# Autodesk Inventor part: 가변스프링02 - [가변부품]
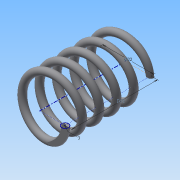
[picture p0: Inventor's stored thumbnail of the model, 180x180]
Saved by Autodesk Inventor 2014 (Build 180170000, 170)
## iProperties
Created: 2015-09
Part Number: 가변스프링02 - [가변부품]
Material: 강철, 탄소
Document SubType Name: Modeling
Designer: study
Density: 7.87 g/cm^3
Appearance: 반연마
Mass: 18.8856 g
Surface Area: 32.5491 cm^2
Volume: 2.3997 cm^3
Author: study
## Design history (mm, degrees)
sketch "스케치1"
  geometry: L1 (0, 0)-(11, 0); L2 (11, 0)-(11, 36.411); L3 (11, 36.411)-(0, 36.411); L4 (0, 36.411)-(0, 0); C1 r 1.5 at (11, 0)
  constraints: 8 end point, 2 parallel, 1 centre point, 1 coincident, 1 horizontal, 1 perpendicular
  dimensions: "d0" = 3 diameter of C1; "d1" = 22 diameter of L2 L4; "d2" = 36.4112 distance of L1.end L2.end (derived)
feature "코일1" pitch "d3" = 10; turns "d5" = 5; dims "d4" = 36.4112 (= d2), "d6" = 0, angle "d7" = 90 deg, angle "d8" = 90 deg, "d9" = 0, "d10" = 0
node "작업 평면1"
sketch "스케치2"
  geometry: L1 (-12.5, 0)-(-9.5, 0) reference; L2 (-12.5, 0)-(-9.5, 0) reference; 1 further point
  constraints: 2 horizontal alignment
extrude "돌출1" cut sketch "스케치2" stored distance "d12" = 10; taper "d13" = 0 deg
node "작업 평면2"
sketch "스케치3"
  geometry: L1 (-9.5, 0)-(-12.5, 0) reference; 1 further point
  constraints: 1 horizontal alignment
extrude "돌출2" cut sketch "스케치3" stored distance "d15" = 10; taper "d16" = 0 deg
node "솔리드1"
node "절단 모서리 투영1"
node "절단 모서리 투영2"
node "절단 모서리 투영3"
other parameters: "d11" = 0, "d14" = 36.4112 (= d2)
